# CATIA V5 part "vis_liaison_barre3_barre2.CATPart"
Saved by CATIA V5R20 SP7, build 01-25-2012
Part number: skl_vis_liaison_barre3_barre2
Bounding box of the stored display mesh (mm): x 2 to 24, y 19.19 to 19.19, z 5.766 to 5.766
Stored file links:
  J:\IFMA\IAO\système avant mef\vis_liaison_barre3_barre2.CATPart
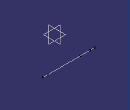
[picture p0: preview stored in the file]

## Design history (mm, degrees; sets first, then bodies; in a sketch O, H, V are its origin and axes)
Body1 (main body)
  Point1 "point_Msecond": stored without definition
  Point2 "Point_M_vis": stored without definition
  Line1: type PtPt, FirstPoint Point1, SecondPoint Point2
  Plane1: stored without definition
  Point3 "Point.Mprim": stored without definition
  Line2 "axe_liason_barre3_barre2": type Normal, RefPoint Point3, RefSkin Plane1, Start 0, End 20
  Plane2: stored without definition
  Point4 "point_Msecond": stored without definition
  Line3 "axe_liaison_barre2_barre3": type Normal, RefPoint Point4, RefSkin Plane2, Start 0, End 20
